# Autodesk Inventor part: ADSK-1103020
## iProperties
Shininess: 50.0
Length Units: 11272
Angle Units: 11279
Time Units: 11290
Mass Units: 11286
Length Display Precision: 4
Angle Display Precision: 2
Compacted: True
Created: 2000-09
Part Number: ADSK-1103020
Document SubType Name: Modeling
Description: DUST BOOT
Mass: 0.811722 g
Surface Area: 17.5384 cm^2
Volume: 0.872819 cm^3
Density: 0.93 g/cm^3
Material: Rubber
Density: 0.0
Volumn: 0.0
Area: 0.0
PropertySet Name: Model Information
Control State: 0
Master: False
Checked Out: False
Author: Autodesk, Inc.
